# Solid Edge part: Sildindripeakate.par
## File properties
Author: Türk
Template: iso part.par
Last saved by: Türk
Revision: 7
Application: Solid Edge
Accuracy: 0,990
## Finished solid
Body 1: solid body, 90 faces, 214 edges, 126 vertices.
  Faces by surface: plane 82, cylinder 8
  Edges by curve: line 204, ellipse 6, circle 4
Bounding box of the edges (mm): 660.000 x 67.500 x 70.528, from (-330, -67.5, -35.2638) to (330, 0, 35.2638).
Cylindrical faces by radius (mm): R10 x8
Planar faces by outward normal: +x 13, +y 5, +z 13, -x 13, -y 21, -z 13, oblique 4
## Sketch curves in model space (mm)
line (-330, -65, -25.2638) -> (-330, -67.5, -25.2638)
line (330, 0, -28.75) -> (330, 0, -28.7118)
line (-330, 0, -28.7118) -> (-330, 0, -28.75)
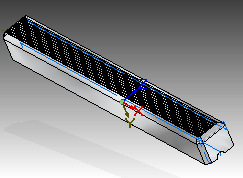
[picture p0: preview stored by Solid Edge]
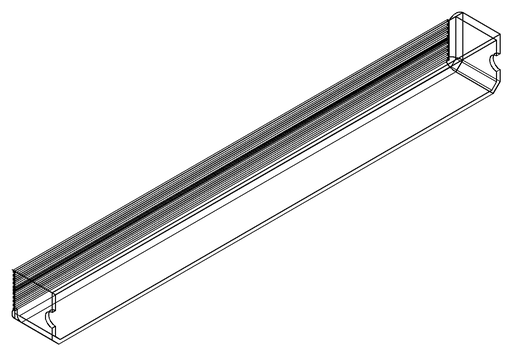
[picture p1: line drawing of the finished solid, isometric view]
